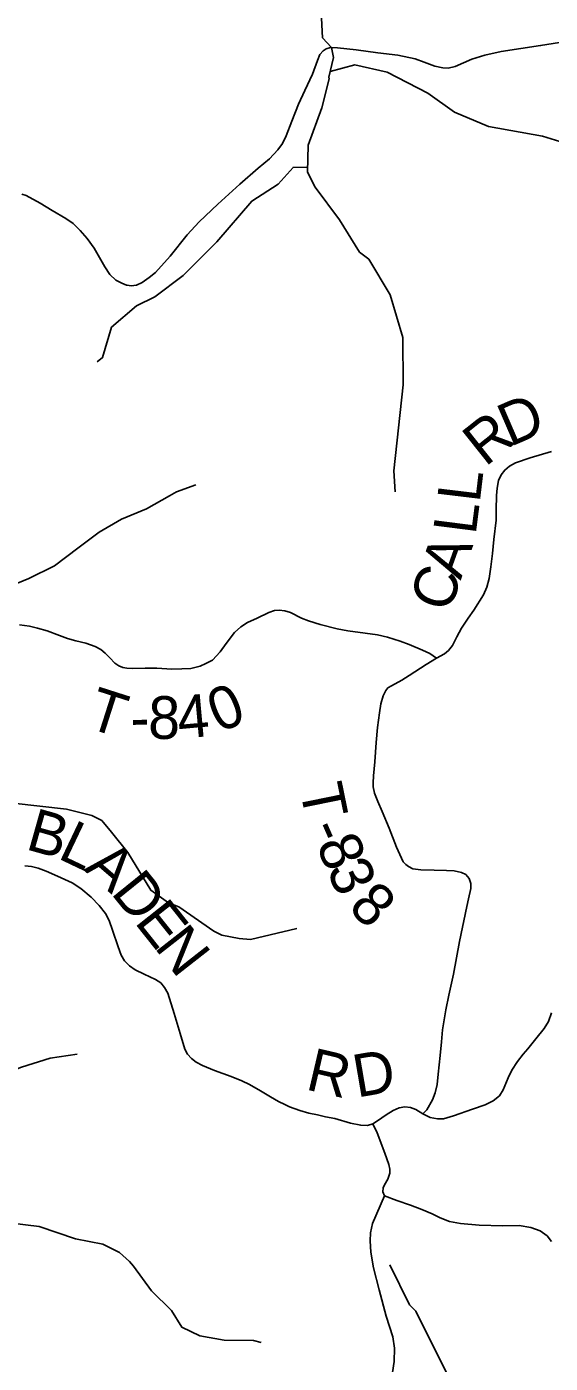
# Model space of a CAD drawing. Extents: x -1.8 to 75.7, y -2 to 25.
# Drawn here: x 47.955 to 48.65, y 16.82 to 18.595 of the extents above; entities that cross this region are included whole.
import ezdxf

# ---------------------------------------------------------------- set-up
doc = ezdxf.new("R2010")
doc.units = 0
for name, color, linetype in [('GM_X_County_Road', 7, 'Continuous'), ('GM_X_County_Road_Text', 7, 'Continuous'), ('GM_X_Minor_River', 7, 'Continuous'), ('GM_X_Township_Road', 7, 'Continuous'), ('GM_X_Township_Road_Text', 7, 'Continuous')]:
    doc.layers.add(name, color=color, linetype=linetype)

msp = doc.modelspace()

# ---------------------------------------------------------------- linework, layer by layer
at = {"layer": 'GM_X_County_Road'}
for points in [[(47.9527, 17.4804), (47.9617, 17.4796), (47.9705, 17.4775), (47.9809, 17.4732), (47.9958, 17.4667), (48.0153, 17.4578), (48.027, 17.4506), (48.0406, 17.4387), (48.0514, 17.4276), (48.0595, 17.4174), (48.0647, 17.4079), (48.0692, 17.395), (48.0765, 17.3727), (48.0806, 17.3619), (48.0849, 17.3544), (48.0914, 17.3479), (48.0991, 17.3424), (48.111, 17.3366), (48.1259, 17.3296), (48.1332, 17.325), (48.1382, 17.3189), (48.1424, 17.3112), (48.1508, 17.2843), (48.1589, 17.2577), (48.1651, 17.2372), (48.1684, 17.2304), (48.1738, 17.2247), (48.18, 17.2198), (48.1885, 17.2152), (48.2043, 17.2085), (48.2263, 17.2006), (48.2407, 17.1949), (48.2509, 17.1902), (48.2654, 17.1816), (48.2785, 17.1739), (48.2893, 17.1674), (48.2977, 17.1637), (48.3038, 17.1604), (48.3177, 17.1556), (48.3295, 17.1522), (48.3412, 17.1497), (48.3516, 17.1472), (48.364, 17.1448), (48.3851, 17.1389), (48.3984, 17.136), (48.4076, 17.1355), (48.4144, 17.1377), (48.4208, 17.1418), (48.432, 17.1497), (48.4415, 17.1554), (48.4494, 17.159), (48.4569, 17.1603), (48.4646, 17.1594), (48.4716, 17.1569), (48.4811, 17.1509), (48.4904, 17.1461), (48.5003, 17.1445), (48.5084, 17.1447), (48.5218, 17.1484), (48.5468, 17.1572), (48.5637, 17.163), (48.5742, 17.1682), (48.5826, 17.1751), (48.5876, 17.1832), (48.594, 17.1991), (48.5991, 17.2093), (48.6066, 17.2206), (48.6139, 17.2303), (48.6203, 17.2373), (48.6309, 17.2508), (48.642, 17.2643), (48.6475, 17.2738), (48.6517, 17.2853)], [(48.4144, 17.1377), (48.4201, 17.1258), (48.4303, 17.0987), (48.4359, 17.0838), (48.437, 17.0777), (48.437, 17.0722), (48.4346, 17.0642), (48.43, 17.0567), (48.4282, 17.0527), (48.428, 17.0476), (48.4302, 17.0422), (48.4462, 17.0361), (48.4645, 17.0296), (48.4795, 17.0241), (48.4933, 17.0185), (48.5037, 17.0132), (48.5163, 17.0081), (48.531, 17.0055), (48.5555, 17.0033), (48.5869, 17.0024), (48.6088, 17.0026), (48.624, 17), (48.6367, 16.9957), (48.6458, 16.9892), (48.6515, 16.9814)], [(48.4407, 16.8078), (48.443, 16.8224), (48.4432, 16.8401), (48.4412, 16.8549), (48.4322, 16.8823), (48.4231, 16.9174), (48.4154, 16.9464), (48.4117, 16.9673), (48.4109, 16.9825), (48.4115, 16.9931), (48.4142, 17.0055), (48.4302, 17.0422)]]:
    msp.add_lwpolyline(points, dxfattribs=at)
at = {"layer": 'GM_X_Minor_River'}
for points in [[(48.2733, 18.8568), (48.2734, 18.8545), (48.2765, 18.8377), (48.2996, 18.8013), (48.3181, 18.7592), (48.3439, 18.7113), (48.3522, 18.687), (48.3538, 18.657), (48.3523, 18.6319), (48.3466, 18.6064), (48.3478, 18.5802), (48.3595, 18.5673), (48.3622, 18.554), (48.3562, 18.5278), (48.3565, 18.5255), (48.3467, 18.4871), (48.3286, 18.4376), (48.3279, 18.4019), (48.3378, 18.3818), (48.3703, 18.3385), (48.3968, 18.2956), (48.4093, 18.2862), (48.4376, 18.239)], [(48.3577, 18.5354), (48.3905, 18.5445), (48.4337, 18.5347), (48.4873, 18.5065), (48.5228, 18.4814), (48.568, 18.4625), (48.6398, 18.4496), (48.6858, 18.4356), (48.7469, 18.4287), (48.7607, 18.4237), (48.7739, 18.421)], [(48.3281, 18.4085), (48.3086, 18.4081), (48.289, 18.3856), (48.2539, 18.3634), (48.2075, 18.3093), (48.163, 18.2646), (48.1252, 18.2363), (48.101, 18.2241), (48.0678, 18.1958), (48.0559, 18.1555), (48.0487, 18.1497)], [(48.4376, 18.239), (48.4543, 18.1821), (48.4547, 18.1191), (48.4425, 18.0052), (48.444, 17.9774)], [(47.9051, 17.8403), (47.958, 17.8621), (47.992, 17.8789), (48.0229, 17.9022), (48.0513, 17.9235), (48.0811, 17.9411), (48.114, 17.9548), (48.1446, 17.972), (48.154, 17.977), (48.1797, 17.9865)], [(47.704, 17.6862), (47.7124, 17.6613), (47.7354, 17.6348), (47.7598, 17.6197), (47.8008, 17.612), (47.8787, 17.5904), (47.9373, 17.5637), (48.008, 17.5557), (48.0418, 17.5475), (48.0547, 17.5407), (48.0677, 17.5252), (48.0895, 17.498), (48.1198, 17.4481), (48.1434, 17.4315), (48.1571, 17.4262), (48.2033, 17.3938), (48.2139, 17.3885), (48.2371, 17.3841), (48.2523, 17.3827), (48.3137, 17.3974)], [(47.6013, 16.9744), (47.6346, 16.9831), (47.6614, 17.0034), (47.6705, 17.0152), (47.6814, 17.0213), (47.7149, 17.0697), (47.7542, 17.1075), (47.7915, 17.1411), (47.849, 17.1744), (47.9482, 17.2129), (47.9865, 17.2249), (48.0221, 17.2304)], [(47.9318, 17.0064), (47.9718, 17.0017), (48.0197, 16.9853), (48.0561, 16.9781), (48.0781, 16.9671), (48.0917, 16.9549), (48.0968, 16.9487), (48.1207, 16.916), (48.1472, 16.8898), (48.1609, 16.8677), (48.1851, 16.8563), (48.2174, 16.8507), (48.2563, 16.8502), (48.2661, 16.8476)], [(48.675, 16.5965), (48.6436, 16.6309), (48.6355, 16.638), (48.5908, 16.6994), (48.5684, 16.721), (48.5438, 16.7582), (48.5128, 16.8063), (48.4718, 16.8889), (48.463, 16.8975), (48.437, 16.9504)]]:
    msp.add_lwpolyline(points, dxfattribs=at)
at = {"layer": 'GM_X_Township_Road'}
for points in [[(48.0883, 18.2516), (48.0939, 18.2508), (48.1007, 18.2517), (48.1086, 18.2551), (48.1178, 18.2617), (48.1262, 18.2684), (48.1456, 18.2904), (48.1681, 18.3184), (48.1842, 18.336), (48.2086, 18.3591), (48.2379, 18.3858), (48.2623, 18.4072), (48.2775, 18.4196), (48.2886, 18.4312), (48.2946, 18.4398), (48.2997, 18.4502), (48.3068, 18.4695), (48.3158, 18.4922), (48.3243, 18.5104), (48.3344, 18.5318), (48.3409, 18.5501), (48.3444, 18.5581), (48.3485, 18.563), (48.3528, 18.5656), (48.3583, 18.5675), (48.3675, 18.5671), (48.3924, 18.5641), (48.421, 18.5604), (48.4476, 18.5572), (48.4705, 18.5521), (48.4827, 18.548), (48.497, 18.5427), (48.5075, 18.5405), (48.5143, 18.5399), (48.5238, 18.542), (48.546, 18.552), (48.5633, 18.5572), (48.5847, 18.5619), (48.6372, 18.5699), (48.6622, 18.5741)], [(47.9487, 18.3725), (47.9546, 18.3708), (47.9732, 18.3604), (47.989, 18.3509), (48.007, 18.3402), (48.0166, 18.3334), (48.0262, 18.3244), (48.0352, 18.3137), (48.0446, 18.3007), (48.059, 18.2761), (48.0654, 18.266), (48.0733, 18.2585), (48.0815, 18.2544), (48.0877, 18.2517), (48.0883, 18.2516)], [(48.4811, 17.1509), (48.486, 17.1565), (48.4935, 17.1696), (48.4974, 17.1791), (48.4998, 17.1901), (48.5012, 17.2039), (48.5037, 17.2286), (48.5055, 17.2469), (48.507, 17.2627), (48.5114, 17.2891), (48.5154, 17.3087), (48.5215, 17.3365), (48.5294, 17.3802), (48.5391, 17.4264), (48.5414, 17.4366), (48.5445, 17.4504), (48.5446, 17.457), (48.5425, 17.4637), (48.538, 17.4689), (48.5323, 17.4718), (48.5224, 17.4737), (48.5123, 17.4743), (48.4958, 17.4746), (48.4781, 17.475), (48.4677, 17.4764), (48.4619, 17.4795), (48.4583, 17.4822), (48.4547, 17.4859), (48.4461, 17.5053), (48.4361, 17.5306), (48.4271, 17.5527), (48.421, 17.5659), (48.4169, 17.5771), (48.4151, 17.5855), (48.4149, 17.5907), (48.4156, 17.5999), (48.4172, 17.6185), (48.4189, 17.6444), (48.4207, 17.6641), (48.4232, 17.6835), (48.4251, 17.6957), (48.4282, 17.7064), (48.4316, 17.7134), (48.4345, 17.7167), (48.4393, 17.7194), (48.4528, 17.727), (48.4626, 17.7332), (48.4854, 17.7481), (48.4989, 17.7563), (48.5098, 17.7621), (48.5151, 17.7666), (48.5202, 17.773), (48.526, 17.7847), (48.5321, 17.796), (48.541, 17.8094), (48.5484, 17.8202), (48.5616, 17.8404), (48.5657, 17.8504), (48.5687, 17.862), (48.5713, 17.8776), (48.5734, 17.8952), (48.5749, 17.9138), (48.5781, 17.9397), (48.5783, 17.9534), (48.5787, 17.9724), (48.5794, 17.982), (48.5815, 17.9921), (48.5847, 17.9996), (48.5897, 18.0062), (48.5957, 18.0111), (48.6038, 18.0156), (48.6235, 18.0225), (48.6515, 18.0306)], [(47.9455, 17.8006), (47.959, 17.7987), (47.9694, 17.796), (47.9821, 17.7926), (47.9985, 17.7866), (48.0092, 17.7825), (48.0204, 17.7791), (48.0338, 17.7761), (48.046, 17.7719), (48.0535, 17.768), (48.0593, 17.7631), (48.0656, 17.7567), (48.0722, 17.7497), (48.0772, 17.7463), (48.0828, 17.7441), (48.088, 17.7432), (48.0959, 17.7427), (48.1124, 17.7429), (48.1278, 17.743), (48.1476, 17.7418), (48.161, 17.742), (48.173, 17.7427), (48.1854, 17.7457), (48.1931, 17.749), (48.2016, 17.7538), (48.2118, 17.7649), (48.2197, 17.7759), (48.231, 17.7902), (48.2394, 17.7979), (48.248, 17.8037), (48.261, 17.8093), (48.2764, 17.817), (48.2841, 17.8197), (48.2902, 17.8202), (48.2979, 17.8191), (48.3051, 17.817), (48.32, 17.8096), (48.3291, 17.8057), (48.3446, 17.8012), (48.367, 17.7954), (48.3814, 17.7927), (48.4045, 17.7897), (48.4207, 17.7874), (48.4339, 17.7841), (48.4508, 17.7787), (48.4626, 17.7744), (48.4804, 17.7667), (48.4903, 17.7624), (48.4989, 17.7563)]]:
    msp.add_lwpolyline(points, dxfattribs=at)

# ---------------------------------------------------------------- texts
at = {"layer": 'GM_X_County_Road_Text'}
for s, rotation, p in [('B', 344.2757, (47.9522, 17.503)), ('L', 334.585, (47.9947, 17.4912)), ('A', 319.2812, (48.0298, 17.4752)), ('D', 308.9574, (48.0658, 17.4445)), ('E', 308.4476, (48.0971, 17.4057)), ('N', 308.071, (48.1235, 17.3725)), ('R', 346.8887, (48.3238, 17.1839)), ('D', 9.6833, (48.3934, 17.1726))]:
    msp.add_text(s, height=0.0568, rotation=rotation, dxfattribs=at).set_placement(p)
at = {"layer": 'GM_X_Township_Road_Text'}
for s, rotation, p in [('D', 23.3981, (48.5967, 18.0366)), ('R', 38.4867, (48.5636, 18.0096)), ('L', 83.1536, (48.5563, 17.9617)), ('L', 82.7316, (48.5509, 17.9191)), ('A', 70.3854, (48.531, 17.859)), ('C', 70.9646, (48.5158, 17.815)), ('T', 342.2776, (48.0328, 17.6647)), ('0', 22.7305, (48.2103, 17.6567)), ('8', 359.0556, (48.1161, 17.6494)), ('4', 5.1397, (48.1573, 17.6491)), ('-', 1.3506, (48.0935, 17.6489)), ('T', 281.5419, (48.3171, 17.5841)), ('8', 292.476, (48.3388, 17.5089)), ('-', 293.6691, (48.3295, 17.53)), ('3', 293.5432, (48.3526, 17.4755)), ('8', 315.7083, (48.3801, 17.4238))]:
    msp.add_text(s, height=0.0568, rotation=rotation, dxfattribs=at).set_placement(p)

doc.saveas('drawing.dxf')
